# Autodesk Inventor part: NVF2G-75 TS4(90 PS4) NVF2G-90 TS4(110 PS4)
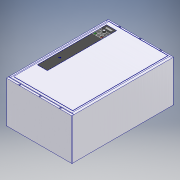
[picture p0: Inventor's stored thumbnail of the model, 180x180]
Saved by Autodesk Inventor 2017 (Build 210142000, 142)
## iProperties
Part Number: NVF2G-75 TS4(90 PS4) NVF2G-90 TS4(110 PS4)
Material: Типовые
Document SubType Name: Modeling
Designer: RSagdiev
Density: 1 g/cm^3
Appearance: По умолчанию
Author: RSagdiev
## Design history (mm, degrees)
sketch "Эскиз1"
  geometry: L1 (0, 0)-(44.679, 0) reference; L2 (0, 0)-(0, 56.035) reference; L3 (0, 0)-(631, 0); L4 (631, 0)-(631, 256.6); L5 (631, 256.6)-(0, 256.6); L6 (0, 256.6)-(0, 0)
  constraints: 12 end point, 3 horizontal, 2 parallel, 2 vertical, 1 perpendicular
  dimensions: "d0" = 631 distance of L5.end L4.end; "d1" = 256.6 distance of L4.end L3.end
extrude "Выдавливание1" new body sketch "Эскиз1" stored distance "d2" = 406; taper "d3" = 0 deg
sketch "Эскиз2"
  geometry: L1 (0, 0)-(0, 631) reference; L2 (406, 0)-(406, 631) reference; L3 (0, 631)-(150, 631); L4 (406, 631)-(406, 619); L5 (406, 0)-(256, 0); L6 (0, 0)-(0, 12); L7 (0, 631)-(406, 631) reference; L8 (0, 631)-(150, 631); L9 (150, 631)-(150, 619); L10 (150, 619)-(0, 619); L11 (0, 619)-(0, 631); L12 (406, 631)-(256, 631); L13 (256, 631)-(256, 619); L14 (256, 619)-(406, 619); L15 (406, 619)-(406, 631); L16 (0, 0)-(406, 0) reference; L17 (0, 0)-(150, 0); L18 (150, 0)-(150, 12); L19 (150, 12)-(0, 12); L20 (0, 12)-(0, 0); L21 (406, 0)-(256, 0); L22 (256, 0)-(256, 12); L23 (256, 12)-(406, 12); L24 (406, 12)-(406, 0); L25 (150, 631)-(256, 631); L26 (0, 619)-(0, 631); L27 (256, 631)-(406, 631); L28 (406, 619)-(406, 12); L29 (256, 0)-(150, 0); L30 (406, 12)-(406, 0); L31 (150, 0)-(0, 0); L32 (0, 12)-(0, 619); L33 (150, 619)-(256, 619); L34 (150, 12)-(256, 12); 1 further point
  constraints: 60 end point, 26 parallel, 13 perpendicular, 7 horizontal
  dimensions: "d4" = 150 distance of L9.end L10.end; "d5" = 12 distance of L3.end L9.end; "d6" = 150 distance of L4.end L13.end; "d7" = 12 distance of L13.end L12.end; "d8" = 150 distance of L6.end L18.end; "d9" = 12 distance of L18.end L17.end; "d10" = 150 distance of L22.end L23.end; "d11" = 12 distance of L5.end L22.end
extrude "Выдавливание2" new body sketch "Эскиз2" distance "d12" = 4; taper "d13" = 0 deg
sketch "Эскиз3"
  geometry: L1 (386, 25)-(386, 615); L2 (20, 615)-(386, 615); L3 (20, 615)-(20, 25); L4 (20, 615)-(386, 615); L5 (20, 25)-(386, 25); L6 (0, 619)-(0, 12) reference; L7 (406, 12)-(406, 619) reference; L8 (0, 631)-(406, 631) reference; L9 (0, 0)-(406, 0) reference; 1 further point
  constraints: 11 end point, 2 perpendicular, 1 horizontal
  dimensions: "d162" = 20 distance between parallel lines of L6 L3 (derived); "d164" = 20 distance between parallel lines of L7 L1; "d203" = 16 distance between parallel lines of L2 L8; "d204" = 25 distance between parallel lines of L9 L5
extrude "Выдавливание3" new body sketch "Эскиз3" distance "d17" = 2; taper "d18" = 0 deg
sketch "Эскиз4"
  geometry: L1 (91, 591)-(32, 591); L2 (30, 589)-(30, 163); L3 (32, 161)-(91, 161); L4 (93, 163)-(93, 589); L5 (0, 631)-(406, 631) reference; L6 (0, 619)-(0, 12) reference; A1 r 2 centre (32, 589) between (32, 591) and (30, 589); A2 r 2 centre (91, 589) between (93, 589) and (91, 591); A3 r 2 centre (91, 163) between (91, 161) and (93, 163); A4 r 2 centre (32, 163) between (30, 163) and (32, 161); 6 further points
  constraints: 8 end point, 8 point on circle, 8 tangent, 6 point on line, 4 centre point, 3 equal radius, 2 parallel, 1 horizontal, 1 perpendicular
  dimensions: "d20" = 63 distance of point (93, 161) point (30, 161); "d21" = 430 distance of point (30, 161) point (30, 591); "d24" = 2 radius of A1; "d165" = 40 distance between parallel lines of L5 L1; "d166" = 30 distance between parallel lines of L6 L2
extrude "Выдавливание4" cut sketch "Эскиз4" distance "d25" = 0.6; taper "d26" = 0 deg
sketch "Эскиз5"
  geometry: L1 (0, 631)-(406, 631) reference; L2 (0, 0)-(0, 631) reference; L3 (406, 631)-(406, 0) reference; L4 (0, 0)-(406, 0) reference; C1 r 5 at (77, 625); C2 r 5 at (203, 625); C3 r 5 at (77, 6); C4 r 5 at (203, 6); C5 r 5 at (329, 625); C6 r 5 at (329, 6); 1 further point
  constraints: 6 centre point
  dimensions: "d27" = 10 diameter of C1; "d28" = 6 distance from line of C1.centre L1; "d30" = 10 diameter of C2; "d31" = 6 distance from line of C2.centre L1; "d33" = 10 diameter of C3; "d34" = 6 distance from line of L4 C3.centre; "d36" = 10 diameter of C4; "d38" = 6 distance from line of C4.centre L4; "d169" = 126 distance of C1.centre C2.centre; "d172" = 126 distance of C4.centre C3.centre (derived); "d205" = 10 diameter of C5; "d206" = 126 distance of C5.centre C2.centre (derived); "d207" = 10 diameter of C6; "d208" = 126 distance of C6.centre C4.centre (derived); "d209" = 406 distance between parallel lines of L3 L2 (derived); "d210" = 77 distance from line of L2 C1.centre (derived); "d211" = 77 distance from line of L2 C3.centre (derived)
extrude "Выдавливание5" cut sketch "Эскиз5" stored distance "d39" = 0.6; taper "d40" = 0 deg
sketch "Эскиз6"
  geometry: L1 (30, 500)-(30, 556); L2 (91, 498)-(32, 498); L3 (93, 589)-(93, 556); L4 (32, 591)-(91, 591); L5 (30, 500)-(30, 589); L6 (30, 556)-(93, 556); L7 (93, 589)-(93, 556); L8 (30, 556)-(30, 589); L9 (93, 556)-(93, 500); L10 (43.5, 567)-(79.5, 567); L11 (81.5, 569)-(81.5, 579); L12 (79.5, 581)-(43.5, 581); L13 (41.5, 579)-(41.5, 569); L14 (41.5, 567)-(81.5, 581); L15 (81.5, 567)-(41.5, 581); L16 (61.5, 544.5)-(61.5, 509.857); L17 (53.25, 544.5)-(53.25, 509.857); L18 (69.75, 509.857)-(69.75, 544.5); L19 (47, 551)-(36, 551); L20 (35, 550)-(35, 539); L21 (36, 538)-(47, 538); L22 (48, 539)-(48, 550); L23 (48, 551)-(35, 538); L24 (35, 551)-(48, 538); L25 (81.5, 569)-(81.5, 504.5); L26 (41.5, 544.5)-(88.409, 544.5); L27 (39.654, 527.179)-(85.729, 527.179); L28 (39.654, 509.857)-(84.963, 509.857); L29 (88, 539)-(88, 550); L30 (76, 538)-(87, 538); L31 (88, 551)-(75, 538); L32 (75, 551)-(88, 538); L33 (75, 550)-(75, 539); L34 (87, 551)-(76, 551); L35 (88, 521.679)-(88, 532.679); L36 (76, 520.679)-(87, 520.679); L37 (88, 533.679)-(75, 520.679); L38 (75, 533.679)-(88, 520.679); L39 (75, 532.679)-(75, 521.679); L40 (87, 533.679)-(76, 533.679); L41 (88, 504.357)-(88, 515.357); L42 (76, 503.357)-(87, 503.357); L43 (88, 516.357)-(75, 503.357); L44 (75, 516.357)-(88, 503.357); L45 (75, 515.357)-(75, 504.357); L46 (87, 516.357)-(76, 516.357); L47 (48, 504.357)-(48, 515.357); L48 (36, 503.357)-(47, 503.357); L49 (48, 516.357)-(35, 503.357); L50 (35, 516.357)-(48, 503.357); L51 (35, 515.357)-(35, 504.357); L52 (47, 516.357)-(36, 516.357); L53 (48, 521.679)-(48, 532.679); L54 (36, 520.679)-(47, 520.679); L55 (48, 533.679)-(35, 520.679); L56 (35, 533.679)-(48, 520.679); L57 (35, 532.679)-(35, 521.679); L58 (47, 533.679)-(36, 533.679); L59 (91, 498)-(32, 498); L60 (0, 631)-(406, 631) reference; L61 (0, 617)-(0, 14); L62 (93, 556)-(93, 500); C1 r 6.5 at (61.5, 544.5); C2 r 6.5 at (61.5, 509.857); C3 r 6.5 at (61.5, 527.179); A1 r 2 centre (43.5, 579) between (43.5, 581) and (41.5, 579); A2 r 2 centre (79.5, 579) between (81.5, 579) and (79.5, 581); A3 r 2 centre (79.5, 569) between (79.5, 567) and (81.5, 569); A4 r 2 centre (43.5, 569) between (41.5, 569) and (43.5, 567); A5 r 8.25 centre (61.5, 544.5) between (69.75, 544.5) and (53.25, 544.5); A6 r 8.25 centre (61.5, 509.857) between (53.25, 509.857) and (69.75, 509.857); A7 r 1 centre (47, 550) between (48, 550) and (47, 551); A8 r 1 centre (47, 539) between (47, 538) and (48, 539); A9 r 1 centre (36, 539) between (35, 539) and (36, 538); A10 r 1 centre (36, 550) between (36, 551) and (35, 550); A11 r 1 centre (87, 539) between (87, 538) and (88, 539); A12 r 1 centre (87, 550) between (88, 550) and (87, 551); A13 r 1 centre (76, 550) between (76, 551) and (75, 550); A14 r 1 centre (76, 539) between (75, 539) and (76, 538); A15 r 1 centre (87, 521.679) between (87, 520.679) and (88, 521.679); A16 r 1 centre (87, 532.679) between (88, 532.679) and (87, 533.679); A17 r 1 centre (76, 532.679) between (76, 533.679) and (75, 532.679); A18 r 1 centre (76, 521.679) between (75, 521.679) and (76, 520.679); A19 r 1 centre (87, 504.357) between (87, 503.357) and (88, 504.357); A20 r 1 centre (87, 515.357) between (88, 515.357) and (87, 516.357); A21 r 1 centre (76, 515.357) between (76, 516.357) and (75, 515.357); A22 r 1 centre (76, 504.357) between (75, 504.357) and (76, 503.357); A23 r 1 centre (47, 504.357) between (47, 503.357) and (48, 504.357); A24 r 1 centre (47, 515.357) between (48, 515.357) and (47, 516.357); A25 r 1 centre (36, 515.357) between (36, 516.357) and (35, 515.357); A26 r 1 centre (36, 504.357) between (35, 504.357) and (36, 503.357); A27 r 1 centre (47, 521.679) between (47, 520.679) and (48, 521.679); A28 r 1 centre (47, 532.679) between (48, 532.679) and (47, 533.679); A29 r 1 centre (36, 532.679) between (36, 533.679) and (35, 532.679); A30 r 1 centre (36, 521.679) between (35, 521.679) and (36, 520.679); A31 r 2 centre (32, 589) between (32, 591) and (30, 589); A32 r 2 centre (91, 589) between (93, 589) and (91, 591); A33 r 2 centre (91, 500) between (91, 498) and (93, 500); A34 r 2 centre (32, 500) between (30, 500) and (32, 498); 15 further points
  constraints: 124 end point, 70 tangent, 68 point on circle, 67 point on line, 37 centre point, 21 equal radius, 15 midpoint, 15 parallel, 11 horizontal, 7 collinear, 7 perpendicular, 3 coincident, 2 vertical
  dimensions: "d43" = 35 distance between parallel lines of L4 L6; "d44" = 40 distance of L15.end L14.end; "d45" = 14 distance of L14.end L15.start; "d46" = 10 distance between parallel lines of L4 L12; "d47" = 2 radius of A1; "d48" = 11.5 distance between parallel lines of L8 L13; "d49" = 16.5 diameter of A6; "d50" = 31.5 distance between parallel lines of L1 L16; "d51" = 11.5 distance from line of L6 L16.start; "d52" = 11.85714 distance from line of L2 L16.end; "d53" = 13 diameter of C1; "d54" = 13 diameter of C2; "d55" = 13 diameter of C3; "d56" = 13 distance of L24.end L23.end; "d57" = 13 distance of L23.end L24.start; "d58" = 1 radius of A7 (derived); "d59" = 11.5 distance from line of L6 L26.start; "d60" = 11.5 distance from line of L5 L26.start; "d61" = 13 distance of L32.end L31.end; "d62" = 13 distance of L31.end L32.start; "d63" = 1 radius of A12 (derived); "d64" = 13 distance of L38.end L37.end; "d65" = 13 distance of L37.end L38.start; "d66" = 1 radius of A16 (derived); "d67" = 13 distance of L44.end L43.end; "d68" = 13 distance of L43.end L44.start; "d69" = 1 radius of A20 (derived); "d70" = 13 distance of L50.end L49.end; "d71" = 13 distance of L49.end L50.start; "d72" = 1 radius of A24 (derived); "d73" = 13 distance of L56.end L55.end; "d74" = 13 distance of L55.end L56.start; "d75" = 1 radius of A28 (derived); "d146" = 40 distance of point (81.5, 544.5) L26.start; "d147" = 4.32143 distance between parallel lines of L40 L30; "d148" = 4.32143 distance between parallel lines of L46 L36; "d149" = 93 distance between parallel lines of L2 L4; "d151" = 2 radius of A31; "d152" = 2 radius of A32; "d153" = 2 radius of A33; "d154" = 2 radius of A34; "d167" = 40 distance between parallel lines of L4 L60 (derived); "d168" = 30 distance between parallel lines of L61 L5 (derived)
extrude "Выдавливание6" new body sketch "Эскиз6" distance "d76" = 0.3; taper "d77" = 0 deg
extrude "Выдавливание7" new body sketch "Эскиз6" distance "d78" = 0.6; taper "d79" = 0 deg
sketch "Эскиз7"
  geometry: L1 (30, 556)-(93, 556) reference; L2 (30, 556)-(93, 556); L3 (93, 556)-(93, 556.1); L4 (93, 556.1)-(30, 556.1); L5 (30, 556.1)-(30, 556); 4 further points; 1 other entity
  constraints: 8 end point, 2 parallel, 1 horizontal, 1 perpendicular, 2 other
  dimensions: "d80" = 0.1 distance of L3.end L2.end
extrude "Выдавливание8" cut sketch "Эскиз7" distance "d81" = 0.3; taper "d82" = 0 deg
sketch "Эскиз8" dims "d91" = 10
  geometry: L1 (30, 556.1)-(93, 556.1) reference; C1 r 1 at (38, 561.1); C2 r 1 at (45.75, 561.1); C3 r 1 at (53.5, 561.1); C4 r 1 at (61.25, 561.1); C5 r 1 at (69, 561.1); C6 r 1 at (76.75, 561.1); C7 r 1 at (84.5, 561.1); 4 further points; 1 other entity
  constraints: 7 centre point, 1 horizontal, 13 other
  dimensions: "d83" = 2 diameter of C1; "d84" = 5 distance from line of C1.centre L1; "d85" = 8 dimension on C1.centre; "d88" = 7.75 distance of C1.centre C2.centre
extrude "Выдавливание9" join sketch "Эскиз8" distance "d93" = 0.3; taper "d94" = 0 deg
sketch "Эскиз9"
  geometry: C1 r 6.5 at (0, 0) reference; C2 r 7.5 at (0, 0); 1 further point
  constraints: 1 centre point, 1 coincident
  dimensions: "d95" = 15 diameter of C2
extrude "Выдавливание10" join sketch "Эскиз9" distance "d96" = 9.4; taper "d97" = -3 deg
sketch "Эскиз10"
  geometry: L1 (0, 7.331)-(0.619, 6.259); L2 (0.619, 6.259)-(-0.619, 6.259); L3 (-0.619, 6.259)-(0, 7.331); 2 further points
  constraints: 6 end point, 7 other
sketch "Эскиз11"
  geometry: L1 (0, 7.917)-(0.884, 6.386); L2 (0.884, 6.386)-(-0.884, 6.386); L3 (-0.884, 6.386)-(0, 7.917); 2 further points
  constraints: 6 end point, 7 other
feature "Лофт1" sketch "Эскиз10", "Эскиз11" dims "d98" = 0, "d99" = 90 deg, "d100" = 0, "d101" = 90 deg
sketch "Эскиз12"
  geometry: L1 (38.419, 546.679)-(44.639, 546.679); L2 (44.639, 546.679)-(44.639, 543.179); L3 (44.639, 543.179)-(38.419, 543.179); L4 (38.419, 543.179)-(38.419, 546.679); L5 (37.47, 529.58)-(46.324, 529.58); L6 (46.324, 529.58)-(46.324, 525.95); L7 (46.324, 525.95)-(37.47, 525.95); L8 (37.47, 525.95)-(37.47, 529.58); L9 (37.113, 512.244)-(46.47, 512.244); L10 (46.47, 512.244)-(46.47, 508.67); L11 (46.47, 508.67)-(37.113, 508.67); L12 (37.113, 508.67)-(37.113, 512.244); L13 (75.942, 512.244)-(87.494, 512.244); L14 (87.494, 512.244)-(87.494, 508.596); L15 (87.494, 508.596)-(75.942, 508.596); L16 (75.942, 508.596)-(75.942, 512.244); L17 (77.723, 529.462)-(85.917, 529.462); L18 (85.917, 529.462)-(85.917, 525.837); L19 (85.917, 525.837)-(77.723, 525.837); L20 (77.723, 525.837)-(77.723, 529.462); L21 (75.823, 546.798)-(88.873, 546.798); L22 (88.873, 546.798)-(88.873, 543.173); L23 (88.873, 543.173)-(75.823, 543.173); L24 (75.823, 543.173)-(75.823, 546.798); 1 further point
  constraints: 12 other
feature "Рельеф1" dims "d4" = 150, "d5" = 12, "d6" = 150, "d7" = 12, "d8" = 150, "d9" = 12, "d10" = 150, "d11" = 12, "d105" = 0.1, "d106" = 0
feature "Рельеф2" dims "d4" = 150, "d5" = 12, "d6" = 150, "d7" = 12, "d8" = 150, "d9" = 12, "d10" = 150, "d11" = 12, "d107" = 0.1, "d108" = 0
feature "Рельеф3" dims "d4" = 150, "d5" = 12, "d6" = 150, "d7" = 12, "d8" = 150, "d9" = 12, "d10" = 150, "d11" = 12, "d109" = 0.1, "d110" = 0
feature "Рельеф4" dims "d4" = 150, "d5" = 12, "d6" = 150, "d7" = 12, "d8" = 150, "d9" = 12, "d10" = 150, "d11" = 12, "d111" = 0.1, "d112" = 0
feature "Рельеф5" dims "d4" = 150, "d5" = 12, "d6" = 150, "d7" = 12, "d8" = 150, "d9" = 12, "d10" = 150, "d11" = 12, "d113" = 0.1, "d114" = 0
feature "Рельеф6" dims "d4" = 150, "d5" = 12, "d6" = 150, "d7" = 12, "d8" = 150, "d9" = 12, "d10" = 150, "d11" = 12, "d115" = 0.1, "d116" = 0
sketch "Эскиз13"
  geometry: L1 (-3.144, -2.347)-(-0.04, 3.728); L2 (-0.04, 3.728)-(3.298, -2.347); L3 (3.298, -2.347)-(2.096, -2.347); L4 (2.096, -2.347)-(-0.04, 1.541); L5 (-0.04, 1.541)-(-2.027, -2.347); L6 (-2.027, -2.347)-(-3.144, -2.347); L7 (-9.387, -8.657)-(8.031, -8.657); L8 (-3.144, -14.967)-(-0.04, -21.041); L9 (-0.04, -21.041)-(3.298, -14.967); L10 (3.298, -14.967)-(2.096, -14.967); L11 (2.096, -14.967)-(-0.04, -18.855); L12 (-0.04, -18.855)-(-2.027, -14.967); L13 (-2.027, -14.967)-(-3.144, -14.967); 1 further point
  constraints: 26 end point, 6 symmetric about line, 2 horizontal, 2 parallel, 2 point on line, 1 collinear
feature "Рельеф7" dims "d4" = 150, "d5" = 12, "d6" = 150, "d7" = 12, "d8" = 150, "d9" = 12, "d10" = 150, "d11" = 12, "d117" = 0.1, "d118" = 0
feature "Рельеф8" dims "d4" = 150, "d5" = 12, "d6" = 150, "d7" = 12, "d8" = 150, "d9" = 12, "d10" = 150, "d11" = 12, "d119" = 0.1, "d120" = 0
sketch "Эскиз14"
  geometry: L1 (62.079, 278.98)-(70.375, 264.61); L2 (70.375, 264.61)-(53.782, 264.61); L3 (53.782, 264.61)-(62.079, 278.98); L4 (68.948, 265.434)-(62.079, 277.332); L5 (62.079, 277.332)-(55.209, 265.434); L6 (55.209, 265.434)-(68.948, 265.434); L7 (61.252, 273.665)-(60.311, 269.855); L8 (60.311, 269.855)-(62.732, 270.025); L9 (62.732, 270.025)-(61.691, 267.709); L10 (61.691, 267.709)-(60.742, 268.135); L11 (60.742, 268.135)-(60.898, 265.905); L12 (60.898, 265.905)-(63.368, 266.954); L13 (63.368, 266.954)-(62.687, 267.261); L14 (62.687, 267.261)-(64.617, 270.896); L15 (64.617, 270.896)-(61.462, 270.713); L16 (61.462, 270.713)-(63.028, 273.665); L17 (63.028, 273.665)-(61.252, 273.665); 2 further points
  constraints: 34 end point, 2 perpendicular, 2 point on line, 1 parallel, 9 other
extrude "Выдавливание11" cut sketch "Эскиз14" distance "d121" = 0.8; taper "d122" = 0 deg
extrude "Выдавливание12" join sketch "Эскиз14" stored distance "d123" = 0.05; taper "d124" = 0 deg
sketch "Эскиз15"
  geometry: L1 (32.937, 564.927)-(57.215, 564.927); L2 (57.215, 564.927)-(57.215, 562.81); L3 (57.215, 562.81)-(32.937, 562.81); L4 (32.937, 562.81)-(32.937, 564.927); L5 (58.162, 564.617)-(88.881, 564.617); L6 (88.881, 564.617)-(88.881, 560.704); L7 (88.881, 560.704)-(58.162, 560.704); L8 (58.162, 560.704)-(58.162, 564.617); L9 (30, 556.1)-(93, 556.1) reference; C1 r 1 at (38, 561.1) reference; 7 further points; 2 other entities
  constraints: 6 other
  dimensions: "d155" = 0.71019 distance edge to line of C1 L3; "d156" = 2.93695 dimension on L4; "d157" = 4.60387 distance between parallel lines of L9 L7; "d158" = 4.11868 dimension on L6
feature "Рельеф9" sketch "Эскиз15" dims "d4" = 150, "d5" = 12, "d6" = 150, "d7" = 12, "d8" = 150, "d9" = 12, "d10" = 150, "d11" = 12, "d125" = 0.1, "d126" = 0
sketch "Эскиз17"
  geometry: L1 (54.534, 359)-(54.534, 352.001); L2 (54.534, 352.001)-(52.465, 352.001); L3 (52.465, 352.001)-(52.465, 359); L4 (52.465, 359)-(54.534, 359); 1 further point
  constraints: 2 other
feature "Рельеф10" sketch "Эскиз17" dims "d4" = 150, "d5" = 12, "d6" = 150, "d7" = 12, "d8" = 150, "d9" = 12, "d10" = 150, "d11" = 12, "d144" = 0.1, "d145" = 0
sketch "Эскиз19" dims "d179" = 10
  geometry: L1 (113.24, 333.958)-(134.375, 351.485); L2 (114.525, 332.409)-(135.66, 349.935); L3 (133.09, 353.034)-(111.955, 335.508); L4 (256.6, 619)-(256.6, 12) reference; L5 (113.24, 323.958)-(134.375, 341.485); L6 (114.525, 322.409)-(135.66, 339.935); L7 (133.09, 343.034)-(111.955, 325.508); L8 (113.24, 313.958)-(134.375, 331.485); L9 (114.525, 312.409)-(135.66, 329.935); L10 (133.09, 333.034)-(111.955, 315.508); L11 (113.24, 303.958)-(134.375, 321.485); L12 (114.525, 302.409)-(135.66, 319.935); L13 (133.09, 323.034)-(111.955, 305.508); L14 (113.24, 293.958)-(134.375, 311.485); L15 (114.525, 292.409)-(135.66, 309.935); L16 (133.09, 313.034)-(111.955, 295.508); L17 (113.24, 283.958)-(134.375, 301.485); L18 (114.525, 282.409)-(135.66, 299.935); L19 (133.09, 303.034)-(111.955, 285.508); L20 (113.24, 273.958)-(134.375, 291.485); L21 (114.525, 272.409)-(135.66, 289.935); L22 (133.09, 293.034)-(111.955, 275.508); L23 (113.24, 263.958)-(134.375, 281.485); L24 (114.525, 262.409)-(135.66, 279.935); L25 (133.09, 283.034)-(111.955, 265.508); L26 (113.24, 253.958)-(134.375, 271.485); L27 (114.525, 252.409)-(135.66, 269.935); L28 (133.09, 273.034)-(111.955, 255.508); L29 (113.24, 243.958)-(134.375, 261.485); L30 (114.525, 242.409)-(135.66, 259.935); L31 (133.09, 263.034)-(111.955, 245.508); A1 r 2.013 centre (113.24, 333.958) between (111.955, 335.508) and (114.525, 332.409); A2 r 2.013 centre (134.375, 351.485) between (135.66, 349.935) and (133.09, 353.034); A3 r 2.013 centre (113.24, 323.958) between (111.955, 325.508) and (114.525, 322.409); A4 r 2.013 centre (134.375, 341.485) between (135.66, 339.935) and (133.09, 343.034); A5 r 2.013 centre (113.24, 313.958) between (111.955, 315.508) and (114.525, 312.409); A6 r 2.013 centre (134.375, 331.485) between (135.66, 329.935) and (133.09, 333.034); A7 r 2.013 centre (113.24, 303.958) between (111.955, 305.508) and (114.525, 302.409); A8 r 2.013 centre (134.375, 321.485) between (135.66, 319.935) and (133.09, 323.034); A9 r 2.013 centre (113.24, 293.958) between (111.955, 295.508) and (114.525, 292.409); A10 r 2.013 centre (134.375, 311.485) between (135.66, 309.935) and (133.09, 313.034); A11 r 2.013 centre (113.24, 283.958) between (111.955, 285.508) and (114.525, 282.409); A12 r 2.013 centre (134.375, 301.485) between (135.66, 299.935) and (133.09, 303.034); A13 r 2.013 centre (113.24, 273.958) between (111.955, 275.508) and (114.525, 272.409); A14 r 2.013 centre (134.375, 291.485) between (135.66, 289.935) and (133.09, 293.034); A15 r 2.013 centre (113.24, 263.958) between (111.955, 265.508) and (114.525, 262.409); A16 r 2.013 centre (134.375, 281.485) between (135.66, 279.935) and (133.09, 283.034); A17 r 2.013 centre (113.24, 253.958) between (111.955, 255.508) and (114.525, 252.409); A18 r 2.013 centre (134.375, 271.485) between (135.66, 269.935) and (133.09, 273.034); A19 r 2.013 centre (113.24, 243.958) between (111.955, 245.508) and (114.525, 242.409); A20 r 2.013 centre (134.375, 261.485) between (135.66, 259.935) and (133.09, 263.034); 13 further points
  constraints: 80 end point, 40 point on circle, 20 centre point, 4 tangent, 1 midpoint, 1 parallel, 1 vertical, 108 other
  dimensions: "d176" = 10 distance of L2.start L6.start
extrude "Выдавливание14" cut sketch "Эскиз19" distance "d181" = 10; taper "d182" = 0 deg
sketch "Эскиз20" dims "d191" = 10, "d198" = 10
  geometry: L1 (256.6, 2)-(0, 2) reference; L2 (0, 631)-(0, 0) reference; C1 r 2 at (15, 132); C2 r 2 at (20, 132); C3 r 2 at (25, 132); C4 r 2 at (30, 132); C5 r 2 at (35, 132); C6 r 2 at (40, 132); C7 r 2 at (45, 132); C8 r 2 at (50, 132); C9 r 2 at (55, 132); C10 r 2 at (60, 132); C11 r 2 at (65, 132); C12 r 2 at (70, 132); C13 r 2 at (70, 127); C14 r 2 at (65, 127); C15 r 2 at (60, 127); C16 r 2 at (55, 127); C17 r 2 at (15, 127); C18 r 2 at (20, 127); C19 r 2 at (25, 127); C20 r 2 at (30, 127); C21 r 2 at (35, 127); C22 r 2 at (40, 127); C23 r 2 at (45, 127); C24 r 2 at (50, 127); C25 r 2 at (70, 122); C26 r 2 at (65, 122); C27 r 2 at (60, 122); C28 r 2 at (55, 122); C29 r 2 at (15, 122); C30 r 2 at (20, 122); C31 r 2 at (25, 122); C32 r 2 at (30, 122); C33 r 2 at (35, 122); C34 r 2 at (40, 122); C35 r 2 at (45, 122); C36 r 2 at (50, 122); C37 r 2 at (70, 117); C38 r 2 at (65, 117); C39 r 2 at (60, 117); C40 r 2 at (55, 117); C41 r 2 at (15, 117); C42 r 2 at (20, 117); C43 r 2 at (25, 117); C44 r 2 at (30, 117); C45 r 2 at (35, 117); C46 r 2 at (40, 117); C47 r 2 at (45, 117); C48 r 2 at (50, 117); C49 r 2 at (70, 112); C50 r 2 at (65, 112); C51 r 2 at (60, 112); C52 r 2 at (55, 112); C53 r 2 at (15, 112); C54 r 2 at (20, 112); C55 r 2 at (25, 112); C56 r 2 at (30, 112); C57 r 2 at (35, 112); C58 r 2 at (40, 112); C59 r 2 at (45, 112); C60 r 2 at (50, 112); C61 r 2 at (70, 107); C62 r 2 at (65, 107); C63 r 2 at (60, 107); C64 r 2 at (55, 107)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; 1 further point
  constraints: 240 centre point, 1 horizontal, 1 vertical, 478 other
  dimensions: "d183" = 4 diameter of C1; "d184" = 15 distance from line of L2 C1.centre; "d185" = 130 distance from line of L1 C1.centre; "d188" = 5 distance of C1.centre C2.centre; "d195" = 5 distance of C12.centre C13.centre
extrude "Выдавливание15" cut sketch "Эскиз20" distance "d200" = 15; taper "d201" = 0 deg
fillet "Сопряжение3" dims "d212" = 20
fillet "Сопряжение4" dims "d213" = 2
node "Твердое тело1"
pattern_circular "Круговой массив1" dims angle "d103" = 360 deg
node "Твердое тело2"
node "Твердое тело3"
node "Твердое тело4"
node "Твердое тело5"
